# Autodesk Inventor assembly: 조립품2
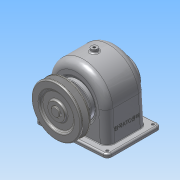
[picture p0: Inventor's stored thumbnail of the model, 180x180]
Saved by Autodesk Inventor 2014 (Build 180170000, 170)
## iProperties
Created: 2016-01
Part Number: 조립품2
Document SubType Name: Assembly
Designer: User
Author: User
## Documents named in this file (16)
- C:\Documents and Settings\User\My Documents\Inventor\20160130\조립품2.iam
- D:\ph\본체2.ipt
- D:\ph\축.ipt
- D:\ph\뒤커버.ipt
- D:\ph\베어링 6203.ipt
- D:\ph\오일씰 28 40 8.ipt
- D:\ph\부시1.ipt
- D:\ph\부시2.ipt
- C:\Documents and Settings\User\My Documents\Inventor\20160130\스퍼기어.ipt
- C:\Documents and Settings\User\My Documents\Inventor\20160130\키 - 6 x 6 x 22.ipt
- C:\Documents and Settings\User\My Documents\Inventor\20160130\키 - 5 x 5 x 18.ipt
- C:\Documents and Settings\User\My Documents\Inventor\20160130\앞커버.ipt
- C:\Documents and Settings\User\My Documents\Inventor\20160130\V-벨트풀리.ipt
- C:\Documents and Settings\User\My Documents\Inventor\20160130\멈춤나사 - M4x10.ipt
- C:\Documents and Settings\User\My Documents\Inventor\20160130\볼트 M3 x 10.ipt
- C:\Documents and Settings\User\My Documents\Inventor\20160130\볼트 M3 x 8.ipt
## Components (9 placed, 3 different names)
1. V-벨트풀리:1
2. ISO 4762 M3 x 8:1
3. ISO 4762 M3 x 10:1
4. ISO 4762 M3 x 8:2
5. ISO 4762 M3 x 10:2
6. ISO 4762 M3 x 8:3
7. ISO 4762 M3 x 10:3
8. ISO 4762 M3 x 8:4
9. ISO 4762 M3 x 10:4
